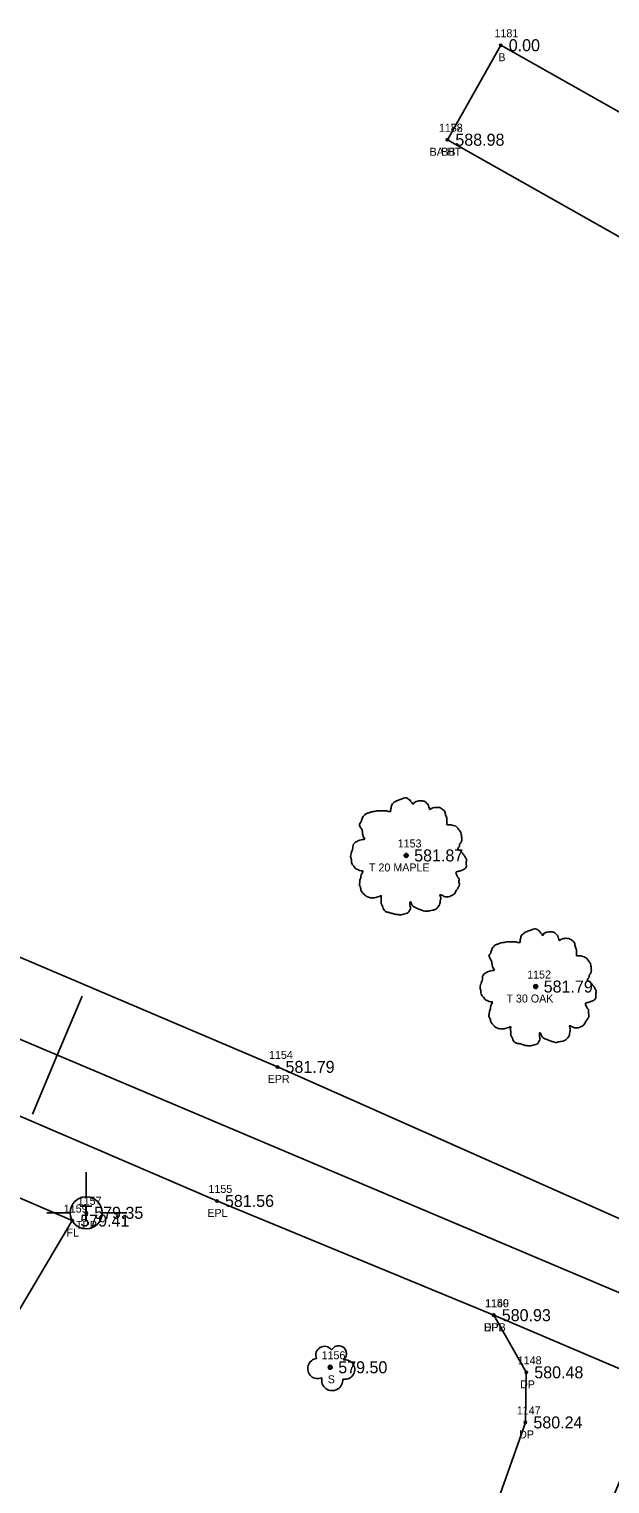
# Model space of a CAD drawing. Extents: x 1664393 to 1667175, y 987029 to 988607.
# Drawn here: x 1665028.1 to 1665100.7, y 987913.2 to 988095 of the extents above; entities that cross this region are included whole.
import ezdxf

# ---------------------------------------------------------------- set-up
doc = ezdxf.new("R2010")
doc.units = 0
for name, color, linetype in [('RD_EX_Bldg', 7, 'Continuous'), ('RD_EX_Bldg_txCode', 7, 'Continuous'), ('RD_EX_Driveway', 7, 'Continuous'), ('RD_EX_Driveway_txCode', 7, 'Continuous'), ('RD_EX_Fence_Other', 7, 'Continuous'), ('RD_EX_Fence_Other_txCode', 7, 'Continuous'), ('RD_EX_Road', 7, 'Continuous'), ('RD_EX_Road_txCode', 7, 'Continuous'), ('RD_EX_TX_Bldg_ELEV', 7, 'Continuous'), ('RD_EX_TX_Driveway_ELEV', 7, 'Continuous'), ('RD_EX_TX_Fence_Other_ELEV', 7, 'Continuous'), ('RD_EX_TX_Road_ELEV', 7, 'Continuous'), ('RD_EX_TX_UT_ELEV', 7, 'Continuous'), ('RD_EX_TX_VEG_ELEV', 7, 'Continuous'), ('RD_EX_UT', 7, 'Continuous'), ('RD_EX_UT_txCode', 7, 'Continuous'), ('RD_EX_VEG', 7, 'Continuous'), ('RD_EX_VEG_txCode', 7, 'Continuous'), ('RD_HC_Cl', 7, 'Continuous'), ('RD_HC_Data_Tic', 7, 'Continuous'), ('RD_SMD_Locator', 7, 'Continuous')]:
    doc.layers.add(name, color=color, linetype=linetype)

msp = doc.modelspace()

# ---------------------------------------------------------------- linework, layer by layer
at = {"layer": 'RD_EX_Bldg'}
msp.add_lwpolyline([(1665080.42, 988081.16), (1665150.45, 988041.63), (1665157.12, 988053.44), (1665087.09, 988092.97), (1665080.42, 988081.16)], dxfattribs=at)
at = {"layer": 'RD_EX_Driveway'}
msp.add_lwpolyline([(1665117.43, 987920.99), (1665108.9, 987920.09), (1665103.43, 987917.07), (1665098.7, 987905.61), (1665086.52, 987910.5), (1665090.17, 987920.87), (1665090.28, 987927.13), (1665086.22, 987934.27)], dxfattribs=at)
at = {"layer": 'RD_EX_Fence_Other'}
msp.add_lwpolyline([(1665020.7, 987924.5), (1665033.54, 987946.09), (1664862.73, 988019.42)], dxfattribs=at)
at = {"layer": 'RD_EX_Road'}
for points in [[(1665506.06, 987776.52), (1665471.95, 987789.57), (1665426.52, 987809.19), (1665380.33, 987828.78), (1665335.61, 987847.53), (1665288.25, 987866.82), (1665242.34, 987886.56), (1665197.07, 987906.16), (1665152.2, 987925.43), (1665127.55, 987936.7), (1665104.5, 987945.2), (1665059.19, 987965.3), (1665013.63, 987984.66), (1664966.38, 988005.06), (1664921.66, 988023.83), (1664875.55, 988043.8)], [(1665498.75, 987759.37), (1665465.87, 987774.2), (1665419.78, 987793.88), (1665373.62, 987813.14), (1665327.95, 987832.31), (1665281.42, 987852.3), (1665236.13, 987871.34), (1665189.6, 987890.71), (1665143.92, 987909.97), (1665117.43, 987920.99), (1665086.22, 987934.27), (1665051.62, 987948.55), (1665005.38, 987968.44), (1664960.17, 987987.67), (1664913.53, 988007.62), (1664868.21, 988026.81)]]:
    msp.add_lwpolyline(points, dxfattribs=at)
at = {"layer": 'RD_EX_UT'}
for p, q in [((1665035.28, 987952.13), (1665035.28, 987949.06)), ((1665030.35, 987947.07), (1665033.28, 987947.07)), ((1665037.28, 987947.07), (1665040.35, 987947.07))]:
    msp.add_line(p, q, dxfattribs=at)
msp.add_circle((1665035.28, 987947.06), 2, dxfattribs=at)
at = {"layer": 'RD_EX_VEG'}
for centre, radius in [((1665075.27, 987991.72), 0.25), ((1665075.26, 987991.7), 0.0001), ((1665091.46, 987975.34), 0.25), ((1665091.44, 987975.32), 0.0001), ((1665065.78, 987927.76), 0.25)]:
    msp.add_circle(centre, radius, dxfattribs=at)
for centre, radius, start, end in [((1665065.06, 987929.3), 1.08, 34.9763, 204.756), ((1665066.83, 987929.46), 0.995, 308.7626, 152.0467), ((1665064.22, 987927.6), 1.26, 96.4518, 294.734), ((1665067.62, 987927.48), 1.22, 256.5667, 98.1046), ((1665066.03, 987926.16), 1.32, 166.8827, 5.7589)]:
    msp.add_arc(centre, radius, start, end, dxfattribs=at)
for points in [[(1665075.4, 987998.88), (1665075.1, 987998.91), (1665074.78, 987998.81), (1665074.53, 987998.71), (1665074.3, 987998.63), (1665074.08, 987998.53), (1665073.78, 987998.36), (1665073.55, 987998.16), (1665073.43, 987997.91), (1665073.38, 987997.68), (1665073.33, 987997.41), (1665073.33, 987997.23), (1665073.2, 987997.21), (1665073.05, 987997.23), (1665072.8, 987997.31), (1665072.55, 987997.31), (1665072.3, 987997.31), (1665071.95, 987997.28), (1665071.6, 987997.28), (1665071.33, 987997.23), (1665071, 987997.18), (1665070.63, 987997.06), (1665070.28, 987996.93), (1665069.98, 987996.68), (1665069.73, 987996.21), (1665069.6, 987995.86), (1665069.45, 987995.61), (1665069.6, 987995.16), (1665069.78, 987994.81), (1665069.8, 987994.61), (1665069.88, 987994.18), (1665069.98, 987993.96), (1665070.1, 987993.76), (1665070.03, 987993.73), (1665069.65, 987993.68), (1665069.35, 987993.58), (1665068.93, 987993.36), (1665068.7, 987993.14), (1665068.6, 987992.81), (1665068.58, 987992.46), (1665068.48, 987992.26), (1665068.4, 987991.99), (1665068.38, 987991.91), (1665068.33, 987991.59), (1665068.43, 987991.14), (1665068.45, 987990.79), (1665068.58, 987990.56), (1665068.73, 987990.39), (1665068.9, 987990.14), (1665069.3, 987989.91), (1665069.63, 987989.81), (1665069.83, 987989.79), (1665069.65, 987989.29), (1665069.6, 987988.94), (1665069.48, 987988.54), (1665069.48, 987988.46), (1665069.43, 987987.99), (1665069.58, 987987.66), (1665069.65, 987987.29), (1665069.83, 987987.06), (1665070.1, 987986.76), (1665070.43, 987986.54), (1665070.93, 987986.41), (1665071.33, 987986.44), (1665071.9, 987986.61), (1665072.15, 987986.69), (1665072.13, 987986.51), (1665072.15, 987986.14), (1665072.15, 987985.71), (1665072.3, 987985.39), (1665072.4, 987985.11), (1665072.55, 987984.86), (1665072.88, 987984.64), (1665073.28, 987984.56), (1665073.7, 987984.41), (1665074.15, 987984.34), (1665074.65, 987984.31), (1665075.25, 987984.46), (1665075.53, 987984.59), (1665075.63, 987984.76), (1665075.83, 987985.14), (1665075.78, 987985.36), (1665075.8, 987985.96), (1665075.9, 987985.79), (1665076.08, 987985.44), (1665076.57, 987985.14), (1665076.97, 987984.96), (1665077.45, 987984.81), (1665077.75, 987984.74), (1665078.22, 987984.81), (1665078.6, 987984.89), (1665078.97, 987985.01), (1665079.27, 987985.29), (1665079.45, 987985.56), (1665079.5, 987985.84), (1665079.57, 987986.21), (1665079.62, 987986.39)], [(1665079.62, 987986.39), (1665079.55, 987986.56), (1665079.5, 987986.81), (1665079.57, 987986.79), (1665079.75, 987986.74), (1665080.02, 987986.61), (1665080.25, 987986.54), (1665080.57, 987986.56), (1665080.85, 987986.66), (1665081.3, 987986.94), (1665081.57, 987987.41), (1665081.85, 987987.81), (1665081.92, 987988.14), (1665081.87, 987988.36), (1665081.85, 987988.86), (1665081.65, 987989.11), (1665081.6, 987989.24), (1665081.5, 987989.64), (1665081.57, 987989.69), (1665081.85, 987989.74), (1665082.22, 987989.86), (1665082.5, 987989.99), (1665082.72, 987990.16), (1665082.8, 987990.39), (1665082.77, 987990.79), (1665082.82, 987991.19), (1665082.75, 987991.34), (1665082.65, 987991.49), (1665082.57, 987991.69), (1665082.42, 987991.84), (1665082.32, 987991.99), (1665082.22, 987992.09), (1665082.1, 987992.24), (1665081.92, 987992.36), (1665081.77, 987992.41), (1665081.72, 987992.56), (1665081.87, 987992.76), (1665081.92, 987992.86), (1665081.95, 987993.09), (1665082.17, 987993.43), (1665082.22, 987993.83), (1665082.17, 987994.26), (1665082.12, 987994.53), (1665081.97, 987994.81), (1665081.77, 987995.06), (1665081.65, 987995.23), (1665081.47, 987995.36), (1665081.15, 987995.48), (1665080.9, 987995.53), (1665080.55, 987995.53), (1665080.35, 987995.58), (1665080.37, 987995.63), (1665080.37, 987995.78), (1665080.37, 987996.06), (1665080.3, 987996.51), (1665080.15, 987997.01), (1665080.15, 987997.03), (1665080.05, 987997.28), (1665079.82, 987997.48), (1665079.65, 987997.58), (1665079.45, 987997.71), (1665079.2, 987997.73), (1665078.9, 987997.73), (1665078.62, 987997.68), (1665078.42, 987997.58), (1665078.25, 987997.46), (1665078.17, 987997.61), (1665078.07, 987997.91), (1665078.02, 987998.06), (1665077.87, 987998.23), (1665077.65, 987998.43), (1665077.2, 987998.56), (1665076.57, 987998.48), (1665076.27, 987998.28), (1665076.12, 987998.11), (1665076.08, 987998.23), (1665075.88, 987998.43), (1665075.78, 987998.61), (1665075.6, 987998.73), (1665075.45, 987998.83), (1665075.35, 987998.88)], [(1665091.59, 987982.51), (1665091.29, 987982.53), (1665090.96, 987982.43), (1665090.71, 987982.33), (1665090.49, 987982.26), (1665090.26, 987982.16), (1665089.96, 987981.98), (1665089.74, 987981.78), (1665089.61, 987981.53), (1665089.56, 987981.31), (1665089.51, 987981.03), (1665089.51, 987980.86), (1665089.39, 987980.83), (1665089.24, 987980.86), (1665088.99, 987980.93), (1665088.74, 987980.93), (1665088.49, 987980.93), (1665088.14, 987980.91), (1665087.79, 987980.91), (1665087.52, 987980.86), (1665087.19, 987980.81), (1665086.82, 987980.68), (1665086.47, 987980.56), (1665086.17, 987980.31), (1665085.92, 987979.83), (1665085.79, 987979.48), (1665085.64, 987979.23), (1665085.79, 987978.78), (1665085.97, 987978.43), (1665085.99, 987978.23), (1665086.07, 987977.81), (1665086.17, 987977.58), (1665086.29, 987977.38), (1665086.22, 987977.36), (1665085.84, 987977.31), (1665085.54, 987977.21), (1665085.12, 987976.98), (1665084.89, 987976.76), (1665084.79, 987976.44), (1665084.77, 987976.09), (1665084.67, 987975.89), (1665084.59, 987975.61), (1665084.57, 987975.54), (1665084.52, 987975.21), (1665084.62, 987974.76), (1665084.64, 987974.41), (1665084.77, 987974.19), (1665084.92, 987974.01), (1665085.09, 987973.76), (1665085.49, 987973.54), (1665085.82, 987973.44), (1665086.02, 987973.41), (1665085.84, 987972.91), (1665085.79, 987972.56), (1665085.67, 987972.16), (1665085.67, 987972.09), (1665085.62, 987971.61), (1665085.77, 987971.29), (1665085.84, 987970.91), (1665086.02, 987970.69), (1665086.29, 987970.39), (1665086.62, 987970.16), (1665087.12, 987970.04), (1665087.52, 987970.06), (1665088.09, 987970.24), (1665088.34, 987970.31), (1665088.31, 987970.14), (1665088.34, 987969.76), (1665088.34, 987969.34), (1665088.49, 987969.01), (1665088.59, 987968.74), (1665088.74, 987968.49), (1665089.06, 987968.26), (1665089.46, 987968.19), (1665089.89, 987968.04), (1665090.34, 987967.96), (1665090.84, 987967.94), (1665091.44, 987968.09), (1665091.71, 987968.21), (1665091.81, 987968.39), (1665092.01, 987968.76), (1665091.96, 987968.99), (1665091.99, 987969.59), (1665092.09, 987969.41), (1665092.26, 987969.06), (1665092.76, 987968.76), (1665093.16, 987968.59), (1665093.64, 987968.44), (1665093.94, 987968.36), (1665094.41, 987968.44), (1665094.79, 987968.51), (1665095.16, 987968.64), (1665095.46, 987968.91), (1665095.64, 987969.19), (1665095.69, 987969.46), (1665095.76, 987969.84), (1665095.81, 987970.01)], [(1665095.81, 987970.01), (1665095.74, 987970.19), (1665095.69, 987970.44), (1665095.76, 987970.41), (1665095.94, 987970.36), (1665096.21, 987970.24), (1665096.44, 987970.16), (1665096.76, 987970.19), (1665097.04, 987970.29), (1665097.49, 987970.56), (1665097.76, 987971.04), (1665098.04, 987971.44), (1665098.11, 987971.76), (1665098.06, 987971.99), (1665098.04, 987972.49), (1665097.84, 987972.74), (1665097.79, 987972.86), (1665097.69, 987973.26), (1665097.76, 987973.31), (1665098.04, 987973.36), (1665098.41, 987973.49), (1665098.69, 987973.61), (1665098.91, 987973.79), (1665098.99, 987974.01), (1665098.96, 987974.41), (1665099.01, 987974.81), (1665098.94, 987974.96), (1665098.84, 987975.11), (1665098.76, 987975.31), (1665098.61, 987975.46), (1665098.51, 987975.61), (1665098.41, 987975.71), (1665098.29, 987975.86), (1665098.11, 987975.99), (1665097.96, 987976.04), (1665097.91, 987976.19), (1665098.06, 987976.39), (1665098.11, 987976.49), (1665098.14, 987976.71), (1665098.36, 987977.06), (1665098.41, 987977.46), (1665098.36, 987977.88), (1665098.31, 987978.16), (1665098.16, 987978.43), (1665097.96, 987978.68), (1665097.84, 987978.86), (1665097.66, 987978.98), (1665097.34, 987979.11), (1665097.09, 987979.16), (1665096.74, 987979.16), (1665096.54, 987979.21), (1665096.56, 987979.26), (1665096.56, 987979.41), (1665096.56, 987979.68), (1665096.49, 987980.13), (1665096.34, 987980.63), (1665096.34, 987980.66), (1665096.24, 987980.91), (1665096.01, 987981.11), (1665095.84, 987981.21), (1665095.64, 987981.33), (1665095.39, 987981.36), (1665095.09, 987981.36), (1665094.81, 987981.31), (1665094.61, 987981.21), (1665094.44, 987981.08), (1665094.36, 987981.23), (1665094.26, 987981.53), (1665094.21, 987981.68), (1665094.06, 987981.86), (1665093.84, 987982.06), (1665093.39, 987982.18), (1665092.76, 987982.11), (1665092.46, 987981.91), (1665092.31, 987981.73), (1665092.26, 987981.86), (1665092.06, 987982.06), (1665091.96, 987982.23), (1665091.79, 987982.36), (1665091.64, 987982.46), (1665091.54, 987982.51)]]:
    msp.add_spline(points, degree=3, dxfattribs=at)
at = {"layer": 'RD_HC_Cl'}
msp.add_line((1666160.05, 987489.41), (1664963.07, 987995.8), dxfattribs=at)
at = {"layer": 'RD_HC_Data_Tic'}
for q in [(1665034.78, 987974.14), (1665028.55, 987959.41)]:
    msp.add_line((1665031.66, 987966.78), q, dxfattribs=at)
at = {"layer": 'RD_SMD_Locator'}
for centre in [(1665087.09, 988092.97), (1665080.42, 988081.16), (1665080.42, 988081.16), (1665075.27, 987991.72), (1665091.46, 987975.34), (1665059.19, 987965.3), (1665051.62, 987948.55), (1665033.54, 987946.09), (1665035.28, 987947.06), (1665086.22, 987934.27), (1665086.22, 987934.27), (1665065.78, 987927.76), (1665090.28, 987927.13), (1665090.17, 987920.87)]:
    msp.add_circle(centre, 0.15, dxfattribs=at)

# ---------------------------------------------------------------- texts
at = {"layer": 'RD_EX_Bldg_txCode'}
for s, p in [('1181', (1665086.31, 988093.97)), ('B', (1665086.79, 988090.97)), ('1178', (1665079.36, 988082.16)), ('1182', (1665079.36, 988082.16)), ('BA HT', (1665078.2, 988079.16)), ('BB', (1665079.65, 988079.16))]:
    msp.add_text(s, height=1, dxfattribs=at).set_placement(p)
at = {"layer": 'RD_EX_Driveway_txCode'}
for s, p in [('1149', (1665085.15, 987935.27)), ('DPB', (1665084.97, 987932.27)), ('1148', (1665089.22, 987928.13)), ('DP', (1665089.5, 987925.13)), ('1147', (1665089.1, 987921.87)), ('DP', (1665089.39, 987918.87))]:
    msp.add_text(s, height=1, dxfattribs=at).set_placement(p)
at = {"layer": 'RD_EX_Fence_Other_txCode'}
for s, p in [('1159', (1665032.48, 987947.09)), ('FL', (1665032.81, 987944.09))]:
    msp.add_text(s, height=1, dxfattribs=at).set_placement(p)
at = {"layer": 'RD_EX_Road_txCode'}
for s, p in [('1154', (1665058.13, 987966.3)), ('EPR', (1665057.96, 987963.3)), ('1155', (1665050.56, 987949.55)), ('EPL', (1665050.42, 987946.55)), ('1150', (1665085.12, 987935.27)), ('EPL', (1665085.01, 987932.27))]:
    msp.add_text(s, height=1, dxfattribs=at).set_placement(p)
at = {"layer": 'RD_EX_TX_Bldg_ELEV'}
for s, p in [('0.00', (1665088.09, 988092.22)), ('588.98', (1665081.42, 988080.41)), ('588.98', (1665081.42, 988080.41))]:
    msp.add_text(s, height=1.5, dxfattribs=at).set_placement(p)
at = {"layer": 'RD_EX_TX_Driveway_ELEV'}
for s, p in [('580.93', (1665087.22, 987933.52)), ('580.48', (1665091.28, 987926.38)), ('580.24', (1665091.17, 987920.12))]:
    msp.add_text(s, height=1.5, dxfattribs=at).set_placement(p)
at = {"layer": 'RD_EX_TX_Fence_Other_ELEV'}
msp.add_text('579.41', height=1.5, dxfattribs=at).set_placement((1665034.54, 987945.34))
at = {"layer": 'RD_EX_TX_Road_ELEV'}
for s, p in [('581.79', (1665060.19, 987964.55)), ('581.56', (1665052.62, 987947.8)), ('580.93', (1665087.22, 987933.52))]:
    msp.add_text(s, height=1.5, dxfattribs=at).set_placement(p)
at = {"layer": 'RD_EX_TX_UT_ELEV'}
msp.add_text('579.35', height=1.5, dxfattribs=at).set_placement((1665036.28, 987946.31))
at = {"layer": 'RD_EX_TX_VEG_ELEV'}
for s, p in [('581.87', (1665076.27, 987990.97)), ('581.79', (1665092.46, 987974.59)), ('579.50', (1665066.78, 987927.01))]:
    msp.add_text(s, height=1.5, dxfattribs=at).set_placement(p)
at = {"layer": 'RD_EX_UT'}
msp.add_text('T', height=2, dxfattribs=at).set_placement((1665034.43, 987946.01))
at = {"layer": 'RD_EX_UT_txCode'}
for s, p in [('1157', (1665034.22, 987948.06)), ('TPP', (1665034.01, 987945.06))]:
    msp.add_text(s, height=1, dxfattribs=at).set_placement(p)
at = {"layer": 'RD_EX_VEG_txCode'}
for s, p in [('1153', (1665074.21, 987992.72)), ('T 20 MAPLE', (1665070.62, 987989.72)), ('1152', (1665090.39, 987976.34)), ('T 30 OAK', (1665087.8, 987973.34)), ('1156', (1665064.7, 987928.76)), ('S', (1665065.47, 987925.76))]:
    msp.add_text(s, height=1, dxfattribs=at).set_placement(p)

doc.saveas('drawing.dxf')
